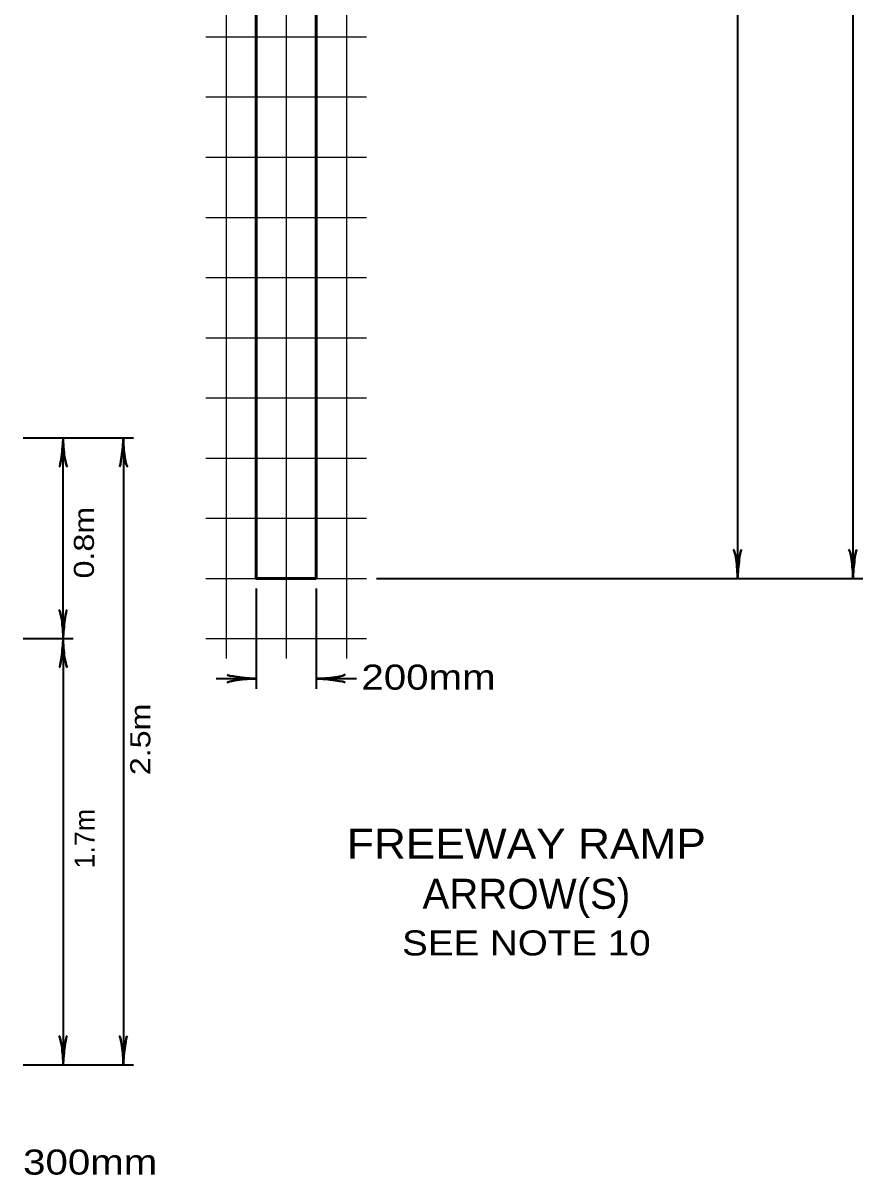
# Model space of a CAD drawing. Extents: x -96 to 617, y -65 to 388.
# Drawn here: x 231.1 to 314.8, y 130.1 to 245 of the extents above; entities that cross this region are included whole.
import ezdxf
from ezdxf.enums import TextEntityAlignment as Align

# ---------------------------------------------------------------- set-up
doc = ezdxf.new("R2010")
doc.units = 0
doc.layers.add('1', color=7, linetype='Continuous', lineweight=53)

msp = doc.modelspace()

# ---------------------------------------------------------------- linework, layer by layer
at = {"layer": '1', "lineweight": 25}
for p, q in [((251.318, 365.599), (251.318, 181.599)), ((257.318, 365.599), (257.318, 181.599)), ((263.318, 365.599), (263.318, 181.599)), ((249.318, 243.599), (265.318, 243.599)), ((249.318, 237.599), (265.318, 237.599)), ((249.318, 231.599), (265.318, 231.599)), ((249.318, 225.599), (265.318, 225.599)), ((249.318, 219.599), (265.318, 219.599)), ((249.318, 213.599), (265.318, 213.599)), ((249.318, 207.599), (265.318, 207.599)), ((249.318, 201.599), (265.318, 201.599)), ((249.318, 195.599), (265.318, 195.599)), ((249.318, 189.599), (265.318, 189.599)), ((249.318, 183.599), (265.318, 183.599))]:
    msp.add_line(p, q, dxfattribs=at)
at = {"layer": '1', "lineweight": 35}
for p, q in [((313.818, 361.599), (313.818, 189.599)), ((302.318, 309.599), (302.318, 189.599)), ((231.079, 203.599), (242.079, 203.599)), ((235.079, 183.599), (235.079, 203.599)), ((241.079, 203.599), (241.079, 141.099)), ((266.318, 189.599), (314.818, 189.599)), ((254.318, 188.599), (254.318, 178.599)), ((260.318, 188.599), (260.318, 178.599)), ((231.079, 183.599), (236.079, 183.599)), ((235.079, 183.599), (235.079, 141.099)), ((250.318, 179.599), (254.318, 179.599)), ((260.318, 179.599), (264.318, 179.599)), ((231.079, 141.099), (242.079, 141.099))]:
    msp.add_line(p, q, dxfattribs=at)
at = {"layer": '1'}
msp.add_line((254.318, 189.599), (260.318, 189.599), dxfattribs=at)
msp.add_lwpolyline([(260.318, 189.599), (260.318, 309.599), (254.318, 309.599), (254.318, 189.599)], close=True, dxfattribs=at)
at = {"layer": '1', "lineweight": 40}
for centre, major_axis, ratio, start_param, end_param in [((234.867, 202.478), (0.176, 1.756), 0.07063, 3.1407148, 5.41811), ((234.867, 202.478), (0.176, 1.756), 0.07063, 3.1407148, 5.41811), ((235.355, 202.507), (-0.156, 1.786), 0.122415, 0.8963533, 3.1415927), ((235.355, 202.507), (-0.156, 1.786), 0.122415, 0.8963533, 3.1415927), ((240.867, 202.478), (0.176, 1.756), 0.07063, 3.1407148, 5.41811), ((241.355, 202.507), (-0.156, 1.786), 0.122415, 0.8963533, 3.1415927), ((302.042, 190.69), (0.156, -1.786), 0.122415, 0.8963533, 3.1415927), ((302.042, 190.69), (0.156, -1.786), 0.122415, 0.8963533, 3.1415927), ((302.53, 190.719), (-0.176, -1.756), 0.07063, 3.1407148, 5.41811), ((302.53, 190.719), (-0.176, -1.756), 0.07063, 3.1407148, 5.41811), ((313.542, 190.69), (0.156, -1.786), 0.122415, 0.8963533, 3.1415927), ((314.03, 190.719), (-0.176, -1.756), 0.07063, 3.1407148, 5.41811), ((234.802, 184.69), (0.156, -1.786), 0.122415, 0.8963533, 3.1415927), ((234.802, 184.69), (0.156, -1.786), 0.122415, 0.8963533, 3.1415927), ((235.29, 184.719), (-0.176, -1.756), 0.07063, 3.1407148, 5.41811), ((235.29, 184.719), (-0.176, -1.756), 0.07063, 3.1407148, 5.41811), ((234.867, 182.478), (0.176, 1.756), 0.07063, 3.1407148, 5.41811), ((234.867, 182.478), (0.176, 1.756), 0.07063, 3.1407148, 5.41811), ((235.355, 182.507), (-0.156, 1.786), 0.122415, 0.8963533, 3.1415927), ((235.355, 182.507), (-0.156, 1.786), 0.122415, 0.8963533, 3.1415927), ((253.227, 179.322), (1.786, 0.156), 0.122415, 0.8963533, 3.1415927), ((253.227, 179.322), (1.786, 0.156), 0.122415, 0.8963533, 3.1415927), ((253.198, 179.81), (1.756, -0.176), 0.07063, 3.1407148, 5.41811), ((253.198, 179.81), (1.756, -0.176), 0.07063, 3.1407148, 5.41811), ((261.409, 179.875), (-1.786, -0.156), 0.122415, 0.8963533, 3.1415927), ((261.409, 179.875), (-1.786, -0.156), 0.122415, 0.8963533, 3.1415927), ((261.439, 179.387), (-1.756, 0.176), 0.07063, 3.1407148, 5.41811), ((261.439, 179.387), (-1.756, 0.176), 0.07063, 3.1407148, 5.41811), ((234.802, 142.19), (0.156, -1.786), 0.122415, 0.8963533, 3.1415927), ((234.802, 142.19), (0.156, -1.786), 0.122415, 0.8963533, 3.1415927), ((235.29, 142.219), (-0.176, -1.756), 0.07063, 3.1407148, 5.41811), ((235.29, 142.219), (-0.176, -1.756), 0.07063, 3.1407148, 5.41811), ((240.802, 142.19), (0.156, -1.786), 0.122415, 0.8963533, 3.1415927), ((240.802, 142.19), (0.156, -1.786), 0.122415, 0.8963533, 3.1415927), ((241.29, 142.219), (-0.176, -1.756), 0.07063, 3.1407148, 5.41811), ((241.29, 142.219), (-0.176, -1.756), 0.07063, 3.1407148, 5.41811)]:
    msp.add_ellipse(centre, major_axis=major_axis, ratio=ratio, start_param=start_param, end_param=end_param, dxfattribs=at)

# ---------------------------------------------------------------- texts
at = {"layer": '1', "width": 1.2}
for s, p in [('0.8m', (238.147, 193.159)), ('2.5m', (243.769, 173.541))]:
    msp.add_text(s, height=2, rotation=90, dxfattribs=at).set_placement(p, align=Align.CENTER)
at = {"layer": '1'}
for s, height, width, p in [('200mm', 2.5, 1.2, (271.505, 178.5)), ('FREEWAY RAMP', 3, 1.1, (281.261, 161.647)), ('SEE NOTE 10', 2.5, 1.15, (281.261, 151.995)), ('300mm', 2.5, 1.2, (237.774, 130.144))]:
    msp.add_text(s, height=height, dxfattribs=dict(at, width=width)).set_placement(p, align=Align.CENTER)
msp.add_text('1.7m', height=2, rotation=90, dxfattribs=at).set_placement((238.212, 163.645), align=Align.CENTER)
msp.add_text('ARROW(S)', height=3, dxfattribs=at).set_placement((281.261, 156.647), align=Align.CENTER)

doc.saveas('drawing.dxf')
